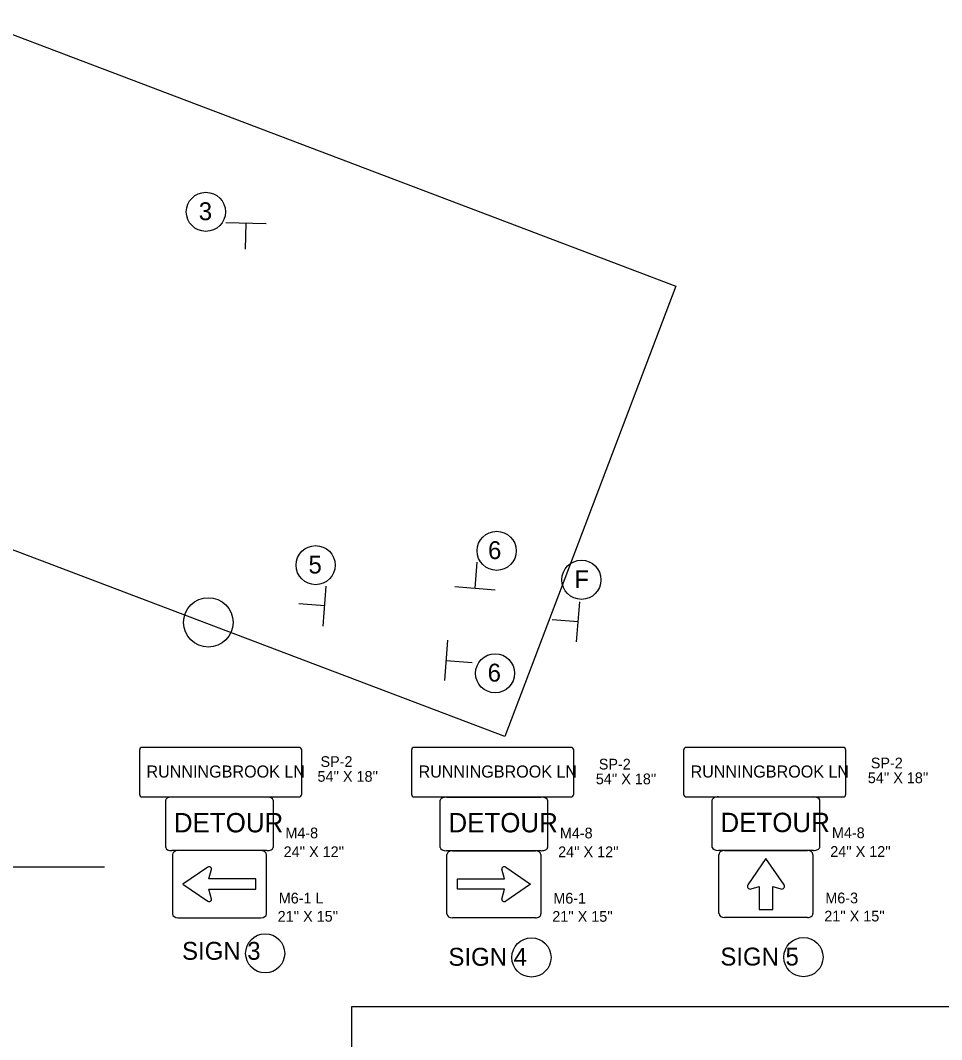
# Model space of a CAD drawing. Extents: x 1615234 to 1620694, y 898143 to 902846.
# Drawn here: x 1618110 to 1619221, y 900086 to 901317 of the extents above; entities that cross this region are included whole.
import ezdxf

# ---------------------------------------------------------------- set-up
doc = ezdxf.new("R2010")
doc.units = 0
for name, color, linetype in [('Default', 7, 'Continuous'), ('DEV STATIONARY SIGN CELL', 7, 'Continuous'), ('DEV TYPE 3 BARRICADE WITH R11-3 M4-10L CELL', 7, 'Continuous'), ('Old_Level_28', 7, 'Continuous'), ('Scratch_Level_0', 7, 'Continuous'), ('WZ INSETA CELL', 7, 'Continuous')]:
    doc.layers.add(name, color=color, linetype=linetype)

msp = doc.modelspace()

# ---------------------------------------------------------------- linework, layer by layer
at = {"layer": 'Default'}
for p, q in [((1618253.3, 900435.7), (1618253.3, 900382.5)), ((1618445.8, 900439), (1618256.6, 900439)), ((1618449.1, 900382.5), (1618449.1, 900435.7)), ((1618581.6, 900435.7), (1618581.6, 900382.5)), ((1618774.1, 900439), (1618584.9, 900439)), ((1618777.4, 900382.5), (1618777.4, 900435.7)), ((1618910, 900435.7), (1618910, 900382.5)), ((1619102.5, 900439), (1618913.3, 900439)), ((1619105.8, 900382.5), (1619105.8, 900435.7)), ((1618256.6, 900379.2), (1618445.8, 900379.2)), ((1618584.9, 900379.2), (1618774.1, 900379.2)), ((1618913.3, 900379.2), (1619102.5, 900379.2))]:
    msp.add_line(p, q, dxfattribs=at)
for centre, start, end in [((1618256.6, 900435.7), 90, 180), ((1618445.8, 900435.7), 0, 90), ((1618584.9, 900435.7), 90, 180), ((1618774.1, 900435.7), 0, 90), ((1618913.3, 900435.7), 90, 180), ((1619102.5, 900435.7), 0, 90), ((1618256.6, 900382.5), 180, 270), ((1618445.8, 900382.5), 270, 0), ((1618584.9, 900382.5), 180, 270), ((1618774.1, 900382.5), 270, 0), ((1618913.3, 900382.5), 180, 270), ((1619102.5, 900382.5), 270, 0)]:
    msp.add_arc(centre, 3.31, start, end, dxfattribs=at)
at = {"layer": 'DEV STATIONARY SIGN CELL'}
for p, q in [((1618406.1, 901071.3), (1618357.5, 901072.7)), ((1618381.6, 901072), (1618380.7, 901040.5)), ((1618658.5, 900631.2), (1618660.9, 900662.6)), ((1618475, 900585.4), (1618478.8, 900633.9)), ((1618634, 900633.2), (1618682.5, 900629.4)), ((1618476.9, 900609.9), (1618445.5, 900612.3)), ((1618780.8, 900566.3), (1618784.6, 900614.8)), ((1618782.7, 900590.8), (1618751.3, 900593.2)), ((1618625.2, 900568.4), (1618621.4, 900519.9)), ((1618623.3, 900543.9), (1618654.7, 900541.5))]:
    msp.add_line(p, q, dxfattribs=at)
at = {"layer": 'DEV TYPE 3 BARRICADE WITH R11-3 M4-10L CELL'}
msp.add_line((1617853.8, 900294.8), (1618211.2, 900294.8), dxfattribs=at)
at = {"layer": 'Old_Level_28'}
for p, q in [((1618349.8, 900314.3), (1618292.5, 900314.3)), ((1618407, 900314.3), (1618349.8, 900314.3)), ((1618681.1, 900314.2), (1618623.9, 900314.2)), ((1618738.3, 900314.2), (1618681.1, 900314.2)), ((1619009.4, 900314.6), (1618952.2, 900314.6)), ((1619066.7, 900314.6), (1619009.4, 900314.6)), ((1618335.6, 900294.4), (1618305.7, 900273.8)), ((1618336.9, 900280.2), (1618340.2, 900291.9)), ((1618694, 900280.1), (1618690.6, 900291.8)), ((1618695.3, 900294.3), (1618725.2, 900273.8)), ((1618305.7, 900273.8), (1618335.6, 900253.2)), ((1618393.9, 900280.2), (1618336.9, 900280.2)), ((1618393.9, 900267.7), (1618393.9, 900280.2)), ((1618637, 900267.6), (1618637, 900280.1)), ((1618637, 900280.1), (1618694, 900280.1)), ((1618725.2, 900273.8), (1618695.3, 900253.2)), ((1618340.2, 900255.8), (1618336.9, 900267.7)), ((1618336.9, 900267.7), (1618393.9, 900267.7)), ((1618694, 900267.6), (1618637, 900267.6)), ((1618690.6, 900255.7), (1618694, 900267.6)), ((1619009.4, 900233.6), (1618959.4, 900233.6)), ((1619059.5, 900233.6), (1619009.4, 900233.6))]:
    msp.add_line(p, q, dxfattribs=at)
for points in [[(1618285, 900318.1), (1618285, 900375.3)], [(1618292.5, 900379.1), (1618349.8, 900379.1)], [(1618349.8, 900379.1), (1618407, 900379.1)], [(1618414.6, 900375.3), (1618414.6, 900318.1)], [(1618616.3, 900318), (1618616.3, 900375.2)], [(1618623.9, 900379), (1618681.1, 900379)], [(1618681.1, 900379), (1618738.3, 900379)], [(1618745.9, 900375.2), (1618745.9, 900318)], [(1618944.6, 900318.3), (1618944.6, 900375.6)], [(1618952.2, 900379.4), (1619009.4, 900379.4)], [(1619009.4, 900379.4), (1619066.7, 900379.4)], [(1619074.2, 900375.6), (1619074.2, 900318.3)], [(1618349.8, 900314.3), (1618299.7, 900314.3)], [(1618399.9, 900314.3), (1618349.8, 900314.3)], [(1618631, 900314.2), (1618681.1, 900314.2)], [(1618681.1, 900314.2), (1618731.2, 900314.2)], [(1618959.4, 900314.6), (1619009.4, 900314.6)], [(1619009.4, 900314.6), (1619059.5, 900314.6)], [(1618293.1, 900309.6), (1618293.1, 900238)], [(1618406.5, 900238), (1618406.5, 900309.6)], [(1618624.4, 900237.9), (1618624.4, 900309.5)], [(1618737.8, 900309.5), (1618737.8, 900237.9)], [(1618952.7, 900238.3), (1618952.7, 900309.8)], [(1619031.2, 900273.1), (1619009.4, 900304.8), (1618987.7, 900273.1)], [(1619031.2, 900273.1), (1619009.4, 900304.8), (1618987.7, 900273.1)], [(1619031.2, 900273.1), (1619009.4, 900304.8), (1618987.7, 900273.1)], [(1619066.1, 900309.8), (1619066.1, 900238.3)], [(1618991.4, 900268.1), (1619001.2, 900271.1), (1619001.2, 900243.3), (1619017.7, 900243.3)], [(1618991.4, 900268.1), (1619001.2, 900271.1), (1619001.2, 900243.3), (1619017.7, 900243.3)], [(1618991.4, 900268.1), (1619001.2, 900271.1), (1619001.2, 900243.3), (1619017.7, 900243.3)], [(1619017.7, 900243.3), (1619017.7, 900271.1), (1619027.5, 900268.1)], [(1619017.7, 900243.3), (1619017.7, 900271.1), (1619027.5, 900268.1)], [(1619017.7, 900243.3), (1619017.7, 900271.1), (1619027.5, 900268.1)], [(1618299.7, 900233.3), (1618349.8, 900233.3)], [(1618349.8, 900233.3), (1618399.9, 900233.3)], [(1618681.1, 900233.2), (1618631, 900233.2)], [(1618731.2, 900233.2), (1618681.1, 900233.2)]]:
    msp.add_lwpolyline(points, dxfattribs=at)
for centre, radius in [((1618333.4, 901085.8), 23.6), ((1618684.4, 900676.4), 23.6), ((1618465.9, 900659.1), 23.6), ((1618786.7, 900641.4), 23.6), ((1618336.4, 900590), 29.8), ((1618682.5, 900528.5), 23.6), ((1618405, 900190.3), 23.6), ((1618726.4, 900185.3), 23.6), ((1619054.7, 900185.7), 23.6)]:
    msp.add_circle(centre, radius, dxfattribs=at)
for centre, start, end in [((1618990.4, 900271.2), 145.5508, 287.601), ((1618990.4, 900271.2), 145.5508, 287.601), ((1618990.4, 900271.2), 145.5508, 287.601), ((1619028.5, 900271.2), 252.399, 34.4492), ((1619028.5, 900271.2), 252.399, 34.4492), ((1619028.5, 900271.2), 252.399, 34.4492)]:
    msp.add_arc(centre, 3.31, start, end, dxfattribs=at)
for centre, major_axis, ratio, start_param, end_param in [((1618292.5, 900375.3), (-7.56, 0), 0.5, 4.712162, 6.283185), ((1618407, 900375.3), (7.56, 0), 0.5, 0, 1.570796), ((1618623.9, 900375.2), (-7.56, 0), 0.5, 4.712162, 6.283185), ((1618738.3, 900375.2), (7.56, 0), 0.5, 0, 1.570796), ((1618952.2, 900375.6), (-7.56, 0), 0.5, 4.712162, 6.283185), ((1619066.7, 900375.6), (7.56, 0), 0.5, 0, 1.570796), ((1618292.5, 900318.1), (-7.56, 0), 0.5, 0, 1.570796), ((1618299.7, 900309.6), (-6.62, 0), 0.714286, 4.712389, 6.283185), ((1618399.9, 900309.6), (6.62, 0), 0.714286, 0, 1.571024), ((1618407, 900318.1), (-7.56, 0), 0.5, 1.570796, 3.141593), ((1618623.9, 900318), (-7.56, 0), 0.5, 0, 1.570796), ((1618631, 900309.5), (-6.62, 0), 0.714286, 4.712162, 6.283185), ((1618731.2, 900309.5), (6.62, 0), 0.714286, 0, 1.570796), ((1618738.3, 900318), (-7.56, 0), 0.5, 1.570796, 3.141593), ((1618952.2, 900318.3), (-7.56, 0), 0.5, 0, 1.570796), ((1618959.4, 900309.8), (-6.61, 0), 0.714286, 4.712162, 6.283185), ((1619059.5, 900309.8), (6.61, 0), 0.714286, 0, 1.570796), ((1619066.7, 900318.3), (-7.56, 0), 0.5, 1.570796, 3.141593), ((1618337.3, 900292.6), (-3.08, 0), 0.720018, 2.830616, 5.313575), ((1618693.6, 900292.5), (3.08, 0), 0.720018, 0.96961, 3.452569), ((1618337.3, 900255.1), (-3.08, 0), 0.720018, 0.969609, 3.452568), ((1618693.6, 900255), (3.08, 0), 0.720018, 2.830617, 5.313577), ((1618299.7, 900238), (6.62, 0), 0.714286, 3.141593, 4.712389), ((1618399.9, 900238), (6.62, 0), 0.714286, 4.712389, 6.283185), ((1618631, 900237.9), (-6.62, 0), 0.714286, 0, 1.570796), ((1618731.2, 900237.9), (-6.62, 0), 0.714286, 1.570796, 3.141593), ((1618959.4, 900238.3), (-6.61, 0), 0.714286, 0, 1.570796), ((1619059.5, 900238.3), (-6.61, 0), 0.714286, 1.570796, 3.141593)]:
    msp.add_ellipse(centre, major_axis=major_axis, ratio=ratio, start_param=start_param, end_param=end_param, dxfattribs=at)
at = {"layer": 'Scratch_Level_0'}
msp.add_lwpolyline([(1620073.1, 902621.2), (1615873.1, 902621.2), (1615873.1, 899771.2), (1618509.6, 899771.2), (1618509.6, 900126), (1620073.1, 900126)], close=True, dxfattribs=at)
at = {"layer": 'WZ INSETA CELL'}
msp.add_lwpolyline([(1616299.4, 901361.3), (1616505.9, 901905.2), (1618900.7, 900996), (1618694.2, 900452.1)], close=True, dxfattribs=at)

# ---------------------------------------------------------------- texts
at = {"layer": 'Default'}
for s in ['panelStyle:construction_guide.ssi', 'panelName:Runningbrook Ln', 'panelQuantity:1', 'panelStation:none', 'panelMaterial:0', 'legendMaterial:0', 'panelMounting:0', 'panelWidthLock:0', 'panelHeightLock:0', 'marginAlign:9', 'panelRoundCorners:0', 'constructPanelMode:0', 'constructPanels:36|24|18', 'panelSizes:', 'panelStandard:2', 'levels:GSCOLORFILL|GSBWFILL|GSOUTLINE', 'version:2', 'widthRounding:6', 'heightRounding:6', 'panelShape:0', 'panelBorderRadius:12.000', 'chevronTipRadius:12.000', 'chevronShoulderRadius:12.000']:
    msp.add_text(s, height=0.00378, dxfattribs=at).set_placement((1618718.9, 900443.1))
at = {"layer": 'Old_Level_28'}
for s, height, p in [('3', 21.6, (1618324.9, 901075.7)), ('6', 21.6, (1618674, 900666.4)), ('5', 21.6, (1618457.3, 900649)), ('F', 21.6, (1618778.2, 900631.4)), ('6', 21.6, (1618673.5, 900518.5)), ('SP-2', 12.96, (1618471.8, 900415.4)), ('SP-2', 12.96, (1618807.7, 900412.3)), ('SP-2', 12.96, (1619136, 900413.7)), ('RUNNINGBROOK LN', 14.552, (1618261.7, 900402.6)), ("54'' X 18''", 12.96, (1618468.2, 900397.5)), ('RUNNINGBROOK LN', 14.552, (1618590.1, 900402.6)), ('RUNNINGBROOK LN', 14.552, (1618918.4, 900402.6)), ("54'' X 18''", 12.96, (1619132.4, 900395.8)), ("54'' X 18''", 12.96, (1618804.1, 900394.5)), ('DETOUR', 23.39, (1618294.8, 900336.4)), ('DETOUR', 23.39, (1618626.2, 900336.4)), ('DETOUR', 23.39, (1618954.5, 900336.7)), ('M4-8', 12.96, (1618429.4, 900329.2)), ('M4-8', 12.96, (1618760.7, 900329.1)), ('M4-8', 12.96, (1619089.1, 900329.4)), ("24'' X 12''", 12.96, (1618427.3, 900306.5)), ("24'' X 12''", 12.96, (1618758.6, 900306.4)), ("24'' X 12''", 12.96, (1619087, 900306.8)), ('M6-1 L', 12.96, (1618421.4, 900250.5)), ('M6-1', 12.96, (1618752.8, 900250.4)), ('M6-3', 12.96, (1619081.1, 900250.7)), ("21'' X 15''", 12.96, (1618420.1, 900228.5)), ("21'' X 15''", 12.96, (1618751.5, 900228.4)), ("21'' X 15''", 12.96, (1619079.8, 900228.8)), ('SIGN 3', 21.6, (1618304.7, 900182.5)), ('SIGN 4', 21.6, (1618626.2, 900175.3)), ('SIGN 5', 21.6, (1618954.4, 900175.6))]:
    msp.add_text(s, height=height, dxfattribs=at).set_placement(p)

doc.saveas('drawing.dxf')
